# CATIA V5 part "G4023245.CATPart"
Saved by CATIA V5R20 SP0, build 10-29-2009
Part number: G4023245
Revision: 5
Definition: design
Nomenclature: G4023245
Source: made
Description: NOT SPECIFIED
Bounding box of the stored display mesh (mm): x -20 to 45, y -22.5 to 22.5, z -22.5 to 22.5
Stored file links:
  C:\Users\Raffaele\Desktop\3D X SITO CF\BOLEX\26-BUSH REF 402\G4023245.CATPart
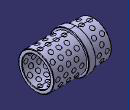
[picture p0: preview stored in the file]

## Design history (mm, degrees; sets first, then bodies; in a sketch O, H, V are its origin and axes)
Body1 "MANIFOLD_SOLID_BREP #11919" (main body)
  Solid1: solid without history
Body2 "MANIFOLD_SOLID_BREP #12074"
  Solid2: solid without history
Body3 "MANIFOLD_SOLID_BREP #12229"
  Solid3: solid without history
Body4 "MANIFOLD_SOLID_BREP #12384"
  Solid4: solid without history
Body5 "MANIFOLD_SOLID_BREP #12541"
  Solid5: solid without history
Body6 "MANIFOLD_SOLID_BREP #12696"
  Solid6: solid without history
Body7 "MANIFOLD_SOLID_BREP #12851"
  Solid7: solid without history
Body8 "MANIFOLD_SOLID_BREP #13008"
  Solid8: solid without history
Body9 "MANIFOLD_SOLID_BREP #13163"
  Solid9: solid without history
Body10 "MANIFOLD_SOLID_BREP #13320"
  Solid10: solid without history
Body11 "MANIFOLD_SOLID_BREP #13477"
  Solid11: solid without history
Body12 "MANIFOLD_SOLID_BREP #13634"
  Solid12: solid without history
Body13 "MANIFOLD_SOLID_BREP #13791"
  Solid13: solid without history
Body14 "MANIFOLD_SOLID_BREP #13948"
  Solid14: solid without history
Body15 "MANIFOLD_SOLID_BREP #14105"
  Solid15: solid without history
Body16 "MANIFOLD_SOLID_BREP #14262"
  Solid16: solid without history
Body17 "MANIFOLD_SOLID_BREP #14419"
  Solid17: solid without history
Body18 "MANIFOLD_SOLID_BREP #14574"
  Solid18: solid without history
Body19 "MANIFOLD_SOLID_BREP #14731"
  Solid19: solid without history
Body20 "MANIFOLD_SOLID_BREP #14886"
  Solid20: solid without history
Body21 "MANIFOLD_SOLID_BREP #15041"
  Solid21: solid without history
Body22 "MANIFOLD_SOLID_BREP #15198"
  Solid22: solid without history
Body23 "MANIFOLD_SOLID_BREP #15353"
  Solid23: solid without history
Body24 "MANIFOLD_SOLID_BREP #15508"
  Solid24: solid without history
Body25 "MANIFOLD_SOLID_BREP #15663"
  Solid25: solid without history
Body26 "MANIFOLD_SOLID_BREP #15818"
  Solid26: solid without history
Body27 "MANIFOLD_SOLID_BREP #15975"
  Solid27: solid without history
Body28 "MANIFOLD_SOLID_BREP #16130"
  Solid28: solid without history
Body29 "MANIFOLD_SOLID_BREP #16285"
  Solid29: solid without history
Body30 "MANIFOLD_SOLID_BREP #16442"
  Solid30: solid without history
Body31 "MANIFOLD_SOLID_BREP #16597"
  Solid31: solid without history
Body32 "MANIFOLD_SOLID_BREP #16752"
  Solid32: solid without history
Body33 "MANIFOLD_SOLID_BREP #16907"
  Solid33: solid without history
Body34 "MANIFOLD_SOLID_BREP #17064"
  Solid34: solid without history
Body35 "MANIFOLD_SOLID_BREP #17221"
  Solid35: solid without history
Body36 "MANIFOLD_SOLID_BREP #17378"
  Solid36: solid without history
Body37 "MANIFOLD_SOLID_BREP #17535"
  Solid37: solid without history
Body38 "MANIFOLD_SOLID_BREP #17692"
  Solid38: solid without history
Body39 "MANIFOLD_SOLID_BREP #17849"
  Solid39: solid without history
Body40 "MANIFOLD_SOLID_BREP #18006"
  Solid40: solid without history
Body41 "MANIFOLD_SOLID_BREP #18163"
  Solid41: solid without history
Body42 "MANIFOLD_SOLID_BREP #18318"
  Solid42: solid without history
Body43 "MANIFOLD_SOLID_BREP #18473"
  Solid43: solid without history
Body44 "MANIFOLD_SOLID_BREP #18630"
  Solid44: solid without history
Body45 "MANIFOLD_SOLID_BREP #18787"
  Solid45: solid without history
Body46 "MANIFOLD_SOLID_BREP #18942"
  Solid46: solid without history
Body47 "MANIFOLD_SOLID_BREP #19097"
  Solid47: solid without history
Body48 "MANIFOLD_SOLID_BREP #19252"
  Solid48: solid without history
Body49 "MANIFOLD_SOLID_BREP #19407"
  Solid49: solid without history
Body50 "MANIFOLD_SOLID_BREP #19564"
  Solid50: solid without history
Body51 "MANIFOLD_SOLID_BREP #19721"
  Solid51: solid without history
Body52 "MANIFOLD_SOLID_BREP #19876"
  Solid52: solid without history
Body53 "MANIFOLD_SOLID_BREP #20031"
  Solid53: solid without history
Body54 "MANIFOLD_SOLID_BREP #20186"
  Solid54: solid without history
Body55 "MANIFOLD_SOLID_BREP #20341"
  Solid55: solid without history
Body56 "MANIFOLD_SOLID_BREP #20496"
  Solid56: solid without history
Body57 "MANIFOLD_SOLID_BREP #20651"
  Solid57: solid without history
Body58 "MANIFOLD_SOLID_BREP #20808"
  Solid58: solid without history
Body59 "MANIFOLD_SOLID_BREP #20965"
  Solid59: solid without history
Body60 "MANIFOLD_SOLID_BREP #21122"
  Solid60: solid without history
Body61 "MANIFOLD_SOLID_BREP #21279"
  Solid61: solid without history
Body62 "MANIFOLD_SOLID_BREP #21436"
  Solid62: solid without history
Body63 "MANIFOLD_SOLID_BREP #21593"
  Solid63: solid without history
Body64 "MANIFOLD_SOLID_BREP #21750"
  Solid64: solid without history
Body65 "MANIFOLD_SOLID_BREP #21907"
  Solid65: solid without history
Body66 "MANIFOLD_SOLID_BREP #22062"
  Solid66: solid without history
Body67 "MANIFOLD_SOLID_BREP #22219"
  Solid67: solid without history
Body68 "MANIFOLD_SOLID_BREP #22374"
  Solid68: solid without history
Body69 "MANIFOLD_SOLID_BREP #22529"
  Solid69: solid without history
Body70 "MANIFOLD_SOLID_BREP #22686"
  Solid70: solid without history
Body71 "MANIFOLD_SOLID_BREP #22841"
  Solid71: solid without history
Body72 "MANIFOLD_SOLID_BREP #22996"
  Solid72: solid without history
Body73 "MANIFOLD_SOLID_BREP #23151"
  Solid73: solid without history
Body74 "MANIFOLD_SOLID_BREP #23308"
  Solid74: solid without history
Body75 "MANIFOLD_SOLID_BREP #23465"
  Solid75: solid without history
Body76 "MANIFOLD_SOLID_BREP #23622"
  Solid76: solid without history
Body77 "MANIFOLD_SOLID_BREP #23779"
  Solid77: solid without history
Body78 "MANIFOLD_SOLID_BREP #23936"
  Solid78: solid without history
Body79 "MANIFOLD_SOLID_BREP #24093"
  Solid79: solid without history
Body80 "MANIFOLD_SOLID_BREP #24250"
  Solid80: solid without history
Body81 "MANIFOLD_SOLID_BREP #24407"
  Solid81: solid without history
